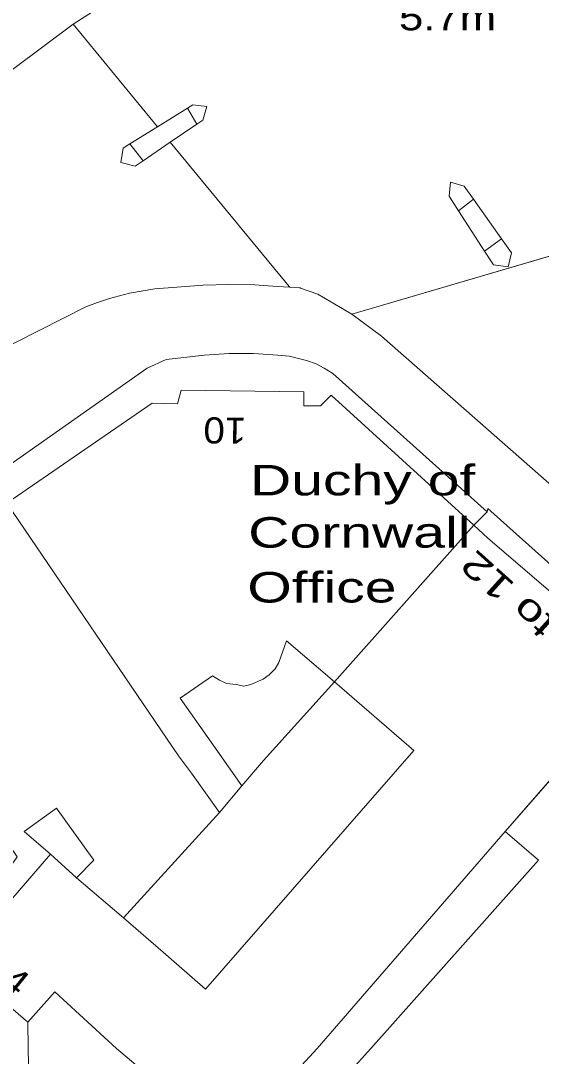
# Model space of a CAD drawing. Extents: x 528790 to 529292, y 179350 to 179856.
# Drawn here: x 529119 to 529148.9, y 179499.5 to 179559 of the extents above; entities that cross this region are included whole.
import ezdxf

# ---------------------------------------------------------------- set-up
doc = ezdxf.new("R2010")
doc.units = 0
doc.header["$LTSCALE"] = 0.6
doc.layers.add('1', color=7, linetype='Continuous', lineweight=13)
doc.layers.add('2', color=7, linetype='Continuous', lineweight=13)
doc.layers.add('5', color=7, linetype='Continuous')

msp = doc.modelspace()

# ---------------------------------------------------------------- linework, layer by layer
at = {"layer": '1'}
for points in [[(529115.6, 179560.6), (529111, 179557.45), (529113.4, 179554), (529113.55, 179553.8), (529113.7, 179553.75), (529113.95, 179553.65), (529114.2, 179553.65), (529114.4, 179553.7), (529114.9, 179553.8), (529115.25, 179554), (529115.7, 179554.2), (529118.6, 179556.25), (529122, 179558.8), (529124.5, 179560.4)], [(529124.5, 179560.4), (529122, 179558.8), (529126.85, 179552.91), (529128.571, 179553.978), (529128.88, 179554.17), (529129.68, 179554.07), (529129.45, 179553.3), (529129.103, 179553.062), (529127.58, 179552.02), (529134.4, 179543.75), (529134.444, 179543.696), (529134.988, 179543.659), (529135.025, 179543.657), (529135.049, 179543.648), (529136.05, 179543.3), (529138, 179542.15), (529153.38, 179546.67)], [(529122, 179558.8), (529118.6, 179556.25)], [(529125.56, 179550.65), (529124.75, 179550.86), (529124.88, 179551.69), (529125.262, 179551.927), (529126.85, 179552.91), (529122, 179558.8)], [(529066.657, 179505.316), (529074.015, 179510.605), (529082.13, 179516.554), (529091.229, 179522.967), (529095.459, 179522.244), (529102.747, 179527.22), (529103.688, 179531.339), (529107.833, 179534.185), (529112.987, 179537.397), (529117.368, 179539.864), (529122.737, 179542.582), (529123.411, 179542.831), (529124.094, 179543.054), (529125.234, 179543.357), (529126.695, 179543.61), (529129.46, 179543.809), (529130.945, 179543.851), (529132.431, 179543.833), (529133.716, 179543.746), (529134.444, 179543.696), (529134.4, 179543.75), (529127.58, 179552.02), (529126.019, 179550.962), (529125.56, 179550.65)], [(529153.38, 179546.67), (529138, 179542.15), (529139.7, 179540.9), (529161.75, 179521.5)], [(529161.75, 179521.5), (529139.7, 179540.9), (529138, 179542.15), (529136.05, 179543.3), (529135.049, 179543.648), (529135.025, 179543.657), (529134.988, 179543.659), (529134.444, 179543.696), (529133.716, 179543.746), (529132.431, 179543.833), (529130.945, 179543.851), (529129.46, 179543.809), (529126.695, 179543.61), (529125.234, 179543.357), (529124.094, 179543.054), (529123.411, 179542.831), (529122.737, 179542.582), (529117.368, 179539.864)], [(529117.2, 179532.7), (529126.25, 179539.05), (529127.35, 179539.55), (529129.55, 179539.8), (529130.95, 179539.9), (529132.35, 179539.9), (529133.75, 179539.8), (529134.4, 179539.75), (529135.4, 179539.5), (529135.95, 179539.3), (529136.4, 179539.05), (529136.9, 179538.75), (529145.75, 179530.8), (529145.8, 179531), (529155.4, 179522.4)], [(529119.45, 179499.1), (529119.43, 179500), (529119.4, 179501.5), (529115.35, 179505), (529116.75, 179506.55), (529116.35, 179506.8), (529116, 179506.55), (529115.7, 179506.3), (529115, 179506.2), (529114.7, 179506.2), (529114.4, 179506.25)]]:
    msp.add_lwpolyline(points, dxfattribs=at)
for points in [[(529127.58, 179552.02), (529129.103, 179553.062), (529128.571, 179553.978), (529126.85, 179552.91), (529125.262, 179551.927), (529126.019, 179550.962)], [(529129.45, 179553.3), (529129.68, 179554.07), (529128.88, 179554.17), (529128.571, 179553.978), (529129.103, 179553.062)], [(529126.019, 179550.962), (529125.262, 179551.927), (529124.88, 179551.69), (529124.75, 179550.86), (529125.56, 179550.65)], [(529144.972, 179548.749), (529144.43, 179549.51), (529143.65, 179549.73), (529143.57, 179548.93), (529144.117, 179548.086)], [(529144.117, 179548.086), (529143.57, 179548.93), (529143.65, 179549.73), (529144.43, 179549.51), (529144.972, 179548.749), (529146.59, 179546.48), (529147.16, 179545.68), (529146.96, 179544.87), (529146.13, 179544.98), (529145.614, 179545.776)], [(529146.59, 179546.48), (529144.972, 179548.749), (529144.117, 179548.086), (529145.614, 179545.776)], [(529147.16, 179545.68), (529146.59, 179546.48), (529145.614, 179545.776), (529146.13, 179544.98), (529146.96, 179544.87)], [(529117.2, 179532.7), (529118.2, 179531.3), (529126.55, 179537.05), (529128, 179537), (529128.2, 179537.8), (529135.25, 179537.7), (529135.25, 179536.9), (529136.2, 179536.9), (529136.8, 179537.5), (529145, 179530.05), (529145.75, 179530.8), (529136.9, 179538.75), (529136.4, 179539.05), (529135.95, 179539.3), (529135.4, 179539.5), (529134.4, 179539.75), (529133.75, 179539.8), (529132.35, 179539.9), (529130.95, 179539.9), (529129.55, 179539.8), (529127.35, 179539.55), (529126.25, 179539.05)], [(529135.25, 179537.7), (529128.2, 179537.8), (529128, 179537), (529126.55, 179537.05), (529118.2, 179531.3), (529128.05, 179516.8), (529128.8, 179515.8), (529130.4, 179513.55), (529131.686, 179515.081), (529130.149, 179517.262), (529129.7, 179517.9), (529128.15, 179520.1), (529130, 179521.4), (529130.4, 179521.15), (529130.8, 179520.95), (529131.35, 179520.9), (529131.8, 179520.8), (529132.2, 179520.9), (529132.9, 179521.2), (529133.25, 179521.45), (529133.6, 179521.8), (529133.8, 179522.15), (529134.25, 179523.4), (529137, 179521.05), (529145, 179530.05), (529136.8, 179537.5), (529136.2, 179536.9), (529135.25, 179536.9)], [(529128.8, 179515.8), (529128.05, 179516.8), (529118.2, 179531.3), (529112.2, 179527.25), (529109.75, 179525.55), (529109.15, 179525.15), (529117.6, 179512.75), (529118.8, 179511), (529117.2, 179508.75), (529117.95, 179507.95), (529120.7, 179511.15), (529119.2, 179512.45), (529121.05, 179513.8), (529123.2, 179510.8), (529122.2, 179509.8), (529124.9, 179507.5), (529130.4, 179513.55)], [(529145.75, 179530.8), (529145, 179530.05), (529145.8, 179529.3), (529151.8, 179524.15), (529154.7, 179521.55), (529155.4, 179522.4), (529145.8, 179531)], [(529146.8, 179512.45), (529154.7, 179521.55), (529151.8, 179524.15), (529145.8, 179529.3), (529145, 179530.05), (529137, 179521.05), (529141.55, 179517.1), (529129.6, 179503.4), (529127.169, 179505.521), (529124.9, 179507.5), (529122.2, 179509.8), (529120.7, 179511.15), (529117.95, 179507.95), (529116.75, 179506.55), (529115.35, 179505), (529119.4, 179501.5), (529120.95, 179503.25), (529124.5, 179500), (529130.929, 179494.567), (529134.9, 179498.8), (529136, 179500)], [(529131.686, 179515.081), (529132.925, 179516.523), (529132.936, 179516.535), (529137, 179521.05), (529134.25, 179523.4), (529133.8, 179522.15), (529133.6, 179521.8), (529133.25, 179521.45), (529132.9, 179521.2), (529132.2, 179520.9), (529131.8, 179520.8), (529131.35, 179520.9), (529130.8, 179520.95), (529130.4, 179521.15), (529130, 179521.4), (529128.15, 179520.1), (529129.7, 179517.9), (529130.149, 179517.262)], [(529150.25, 179497.55), (529152.55, 179500), (529164.2, 179512.9), (529159.65, 179517), (529154.7, 179521.55), (529146.8, 179512.45), (529148.7, 179510.8), (529139.08, 179500), (529136.6, 179497.25), (529134.9, 179498.8), (529130.929, 179494.567), (529138.05, 179488.55), (529140.6, 179491.55), (529142.2, 179490.3), (529142.8, 179491.8), (529144, 179490.8)], [(529141.55, 179517.1), (529137, 179521.05), (529132.936, 179516.535), (529132.925, 179516.523), (529131.686, 179515.081), (529130.4, 179513.55), (529124.9, 179507.5), (529127.169, 179505.521), (529129.6, 179503.4)], [(529120.7, 179511.15), (529122.2, 179509.8), (529123.2, 179510.8), (529121.05, 179513.8), (529119.2, 179512.45)], [(529146.8, 179512.45), (529136, 179500), (529134.9, 179498.8), (529136.6, 179497.25), (529139.08, 179500), (529148.7, 179510.8)], [(529136.75, 179487.15), (529137.25, 179487.6), (529137.7, 179488.05), (529138.05, 179488.55), (529130.929, 179494.567), (529124.5, 179500), (529120.95, 179503.25), (529119.4, 179501.5), (529119.43, 179500), (529119.45, 179499.1), (529125.45, 179495.35), (529131.2, 179490.95), (529133.35, 179488.6), (529136.2, 179486.8)]]:
    msp.add_lwpolyline(points, close=True, dxfattribs=at)
at = {"layer": '2'}
for p, q in [((529126.85, 179552.91), (529122, 179558.8)), ((529126.85, 179552.91), (529128.571, 179553.978)), ((529128.571, 179553.978), (529129.103, 179553.062)), ((529125.262, 179551.927), (529126.85, 179552.91)), ((529129.103, 179553.062), (529127.58, 179552.02)), ((529125.262, 179551.927), (529126.019, 179550.962)), ((529127.58, 179552.02), (529126.019, 179550.962)), ((529144.972, 179548.749), (529144.117, 179548.086)), ((529144.972, 179548.749), (529146.59, 179546.48)), ((529145.614, 179545.776), (529144.117, 179548.086)), ((529138, 179542.15), (529153.38, 179546.67)), ((529146.59, 179546.48), (529145.614, 179545.776)), ((529145.75, 179530.8), (529145, 179530.05)), ((529145, 179530.05), (529137, 179521.05)), ((529146.8, 179512.45), (529154.7, 179521.55)), ((529131.686, 179515.081), (529130.4, 179513.55)), ((529124.9, 179507.5), (529130.4, 179513.55)), ((529120.7, 179511.15), (529117.95, 179507.95)), ((529122.2, 179509.8), (529120.7, 179511.15)), ((529124.9, 179507.5), (529122.2, 179509.8))]:
    msp.add_line(p, q, dxfattribs=at)
for points in [[(529128.25, 179563.8), (529128.05, 179563.55), (529127.9, 179563.3), (529127.6, 179563.05), (529127.4, 179562.75), (529127, 179562.25), (529126.75, 179562.05), (529126.55, 179561.9), (529126.35, 179561.65), (529126.05, 179561.4), (529125.55, 179561.1), (529125.25, 179560.9), (529125, 179560.75), (529124.75, 179560.55), (529124.5, 179560.4), (529122, 179558.8)], [(529122, 179558.8), (529118.6, 179556.25), (529115.7, 179554.2), (529115.25, 179554), (529114.9, 179553.8), (529114.4, 179553.7), (529114.2, 179553.65), (529113.95, 179553.65), (529113.7, 179553.75), (529113.55, 179553.8), (529113.4, 179554), (529111, 179557.45)], [(529128.571, 179553.978), (529128.88, 179554.17), (529129.68, 179554.07), (529129.45, 179553.3), (529129.103, 179553.062)], [(529126.019, 179550.962), (529125.56, 179550.65), (529124.75, 179550.86), (529124.88, 179551.69), (529125.262, 179551.927)], [(529134.444, 179543.696), (529134.4, 179543.75), (529127.58, 179552.02)], [(529144.117, 179548.086), (529143.57, 179548.93), (529143.65, 179549.73), (529144.43, 179549.51), (529144.972, 179548.749)], [(529146.59, 179546.48), (529147.16, 179545.68), (529146.96, 179544.87), (529146.13, 179544.98), (529145.614, 179545.776)], [(529066.657, 179505.316), (529074.015, 179510.605), (529082.13, 179516.554), (529091.229, 179522.967), (529095.459, 179522.244), (529102.747, 179527.22), (529103.688, 179531.339), (529107.833, 179534.185), (529112.987, 179537.397), (529117.368, 179539.864), (529122.737, 179542.582), (529123.411, 179542.831), (529124.094, 179543.054), (529125.234, 179543.357), (529126.695, 179543.61), (529129.46, 179543.809), (529130.945, 179543.851), (529132.431, 179543.833), (529133.716, 179543.746), (529134.444, 179543.696)], [(529134.444, 179543.696), (529134.988, 179543.659), (529135.025, 179543.657), (529135.049, 179543.648), (529136.05, 179543.3), (529138, 179542.15)], [(529138, 179542.15), (529139.7, 179540.9), (529161.75, 179521.5), (529166.4, 179517.55), (529172.2, 179512.8), (529176.6, 179509.45), (529180.15, 179506.8), (529184.9, 179503.45), (529189.7, 179500), (529191.5, 179498.65), (529195.35, 179496.25), (529199.7, 179493.8), (529204.05, 179491.65), (529212.55, 179488.2), (529224, 179483.65), (529235.05, 179479.15), (529236, 179478.25), (529236.2, 179477.8), (529236.4, 179477.3), (529236.55, 179476.8), (529236.55, 179476.4), (529236.5, 179476), (529236.4, 179475.55)], [(529117.2, 179532.7), (529126.25, 179539.05), (529127.35, 179539.55), (529129.55, 179539.8), (529130.95, 179539.9), (529132.35, 179539.9), (529133.75, 179539.8), (529134.4, 179539.75), (529135.4, 179539.5), (529135.95, 179539.3), (529136.4, 179539.05), (529136.9, 179538.75), (529145.75, 179530.8)], [(529145, 179530.05), (529136.8, 179537.5), (529136.2, 179536.9), (529135.25, 179536.9), (529135.25, 179537.7), (529128.2, 179537.8), (529128, 179537), (529126.55, 179537.05), (529118.2, 179531.3)], [(529130.4, 179513.55), (529128.8, 179515.8), (529128.05, 179516.8), (529118.2, 179531.3)], [(529145.75, 179530.8), (529145.8, 179531), (529155.4, 179522.4)], [(529154.7, 179521.55), (529151.8, 179524.15), (529145.8, 179529.3), (529145, 179530.05)], [(529131.686, 179515.081), (529130.149, 179517.262), (529129.7, 179517.9), (529128.15, 179520.1), (529130, 179521.4), (529130.4, 179521.15), (529130.8, 179520.95), (529131.35, 179520.9), (529131.8, 179520.8), (529132.2, 179520.9), (529132.9, 179521.2), (529133.25, 179521.45), (529133.6, 179521.8), (529133.8, 179522.15), (529134.25, 179523.4), (529137, 179521.05)], [(529137, 179521.05), (529141.55, 179517.1), (529129.6, 179503.4), (529127.169, 179505.521), (529124.9, 179507.5)], [(529137, 179521.05), (529132.936, 179516.535), (529132.925, 179516.523), (529131.686, 179515.081)], [(529120.7, 179511.15), (529119.2, 179512.45), (529121.05, 179513.8), (529123.2, 179510.8), (529122.2, 179509.8)], [(529146.8, 179512.45), (529148.7, 179510.8), (529139.08, 179500), (529136.6, 179497.25), (529134.9, 179498.8)], [(529134.9, 179498.8), (529136, 179500), (529146.8, 179512.45)], [(529116.75, 179506.55), (529115.35, 179505), (529119.4, 179501.5)], [(529119.4, 179501.5), (529120.95, 179503.25), (529124.5, 179500), (529130.929, 179494.567)], [(529119.45, 179499.1), (529119.43, 179500), (529119.4, 179501.5)]]:
    msp.add_lwpolyline(points, dxfattribs=at)

# ---------------------------------------------------------------- texts
at = {"layer": '5'}
for s, height, width, p in [('5.7m', 1.5, 1.25, (529140.7, 179558.45)), ('Duchy of', 1.75, 1.4, (529132.15, 179531.75)), ('Cornwall', 1.75, 1.4, (529132.05, 179528.75)), ('Office', 1.75, 1.4, (529132, 179525.6))]:
    msp.add_text(s, height=height, dxfattribs=dict(at, width=width)).set_placement(p)
for s, rotation, width, p in [('10', 179, 1.1, (529131.95, 179536.2)), ('11 to 12', 138, 1.4, (529152.65, 179521.92)), ('24', 321, 1.1, (529116.8, 179504.46))]:
    msp.add_text(s, height=1.5, rotation=rotation, dxfattribs=dict(at, width=width)).set_placement(p)

doc.saveas('drawing.dxf')
